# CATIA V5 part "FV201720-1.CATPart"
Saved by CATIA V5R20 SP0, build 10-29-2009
Part number: FV201720-1
Revision: ANY
Definition: UNKNOWN
Nomenclature: FV201720-1
Source: Unknown
Bounding box of the stored display mesh (mm): x -10 to 10, y -20 to 0, z -10 to 10
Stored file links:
  C:\Users\Utente\Desktop\IO LAVORO\3D X SITO CF\CUMSA\3D files FV\FV 201720\FV201720-1.CATPart
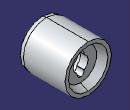
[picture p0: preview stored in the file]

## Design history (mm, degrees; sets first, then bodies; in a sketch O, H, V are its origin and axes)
Body1 "Cortar-Extruir1" (main body)
  Solid1: solid without history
